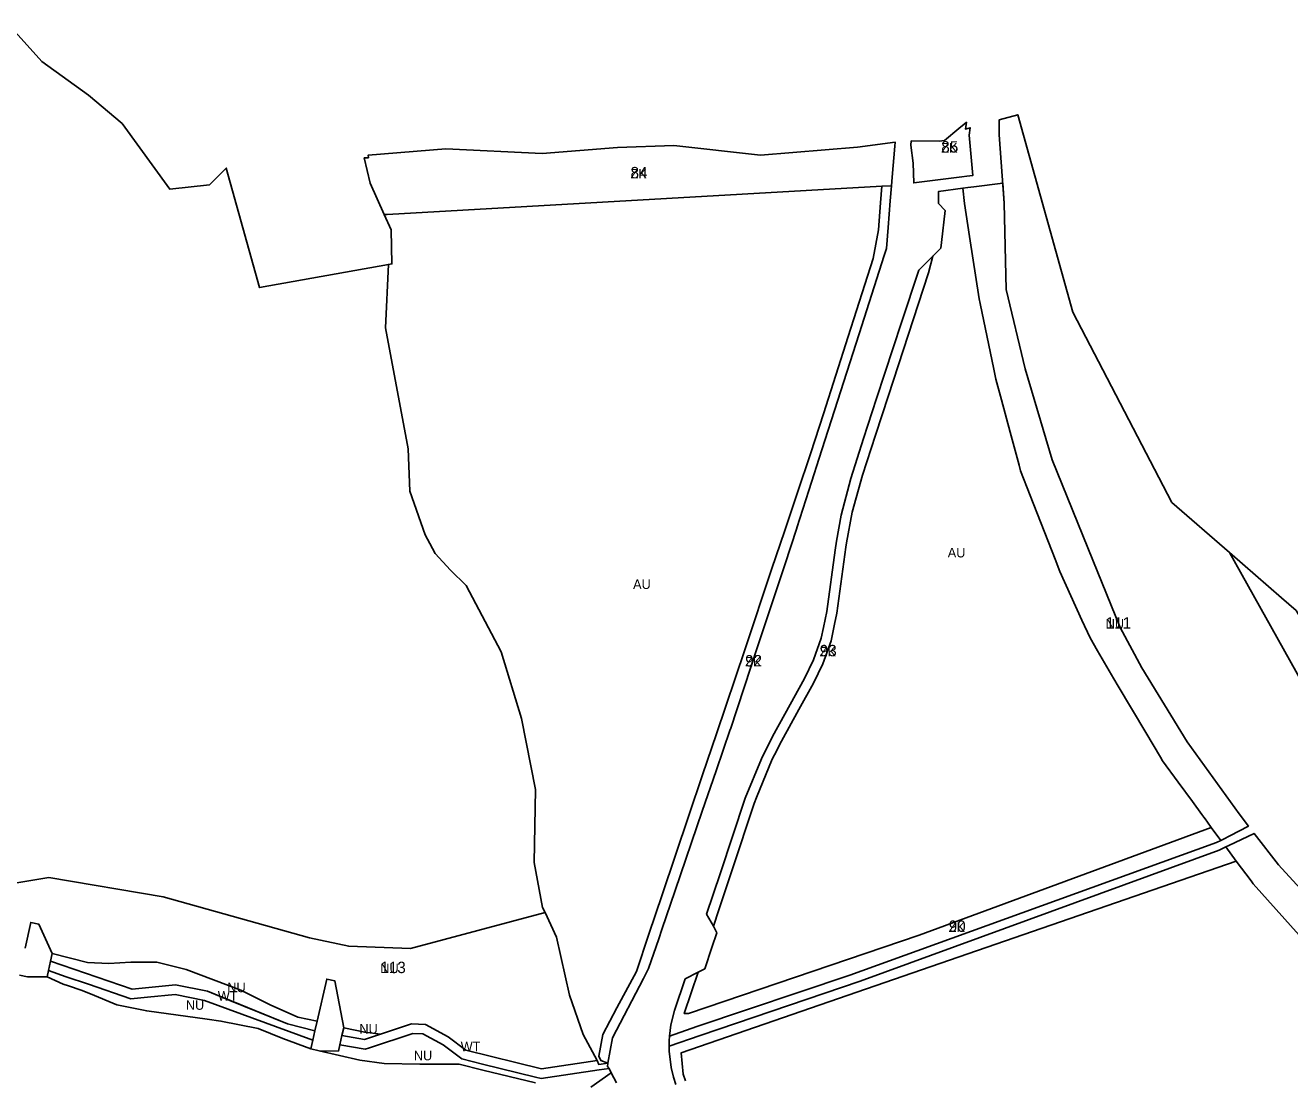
# Model space of a CAD drawing. Extents: x -535894 to -532834, y -1165802 to -1163647.
# Drawn here: x -534347 to -533682, y -1164374 to -1163819 of the extents above; entities that cross this region are included whole.
import ezdxf

# ---------------------------------------------------------------- set-up
doc = ezdxf.new("R2010")
doc.units = 0
for name, color, linetype in [('Vrstva 17', 7, 'Continuous'), ('Vrstva 19', 7, 'Continuous'), ('Vrstva 20', 7, 'Continuous'), ('Vrstva 22', 7, 'Continuous'), ('Vrstva 4', 7, 'Continuous'), ('Vrstva 61', 7, 'Continuous')]:
    doc.layers.add(name, color=color, linetype=linetype)

msp = doc.modelspace()

# ---------------------------------------------------------------- linework, layer by layer
at = {"layer": 'Vrstva 17'}
for points in [[(-533854.784, -1163898.999), (-533880.128, -1163902.177), (-533880.47, -1163891.74), (-533881.62, -1163882.25), (-533881.4, -1163880.05), (-533866.68, -1163880.24), (-533863.98, -1163879.91), (-533856.45, -1163873.6), (-533853.53, -1163871.16), (-533852.38, -1163870.19), (-533852.91, -1163873.85), (-533850.38, -1163873.16), (-533850.88, -1163877.07), (-533849.072, -1163898.259), (-533852.16, -1163898.659)], [(-533891.816, -1163903.599), (-533896.856, -1163903.885), (-534157.028, -1163918.699), (-534158.612, -1163918.789), (-534166.07, -1163902.27), (-534169.16, -1163888.95), (-534166.94, -1163888.88), (-534167.05, -1163887.54), (-534126.29, -1163884.14), (-534075.55, -1163886.63), (-534035.93, -1163883.59), (-534006.23, -1163882.44), (-533960.63, -1163887.47), (-533909.61, -1163883.3), (-533889.94, -1163880.68), (-533890.12, -1163882.84), (-533891.45, -1163899.11)], [(-534019.391, -1164297.188), (-534012.469, -1164276.63), (-533998.41, -1164234.878), (-533991.219, -1164213.523), (-533983.929, -1164191.872), (-533969.039, -1164147.651), (-533954.676, -1164104.997), (-533948.086, -1164085.426), (-533941.36, -1164065.453), (-533934.167, -1164044.089), (-533927.576, -1164023.511), (-533914.601, -1163982.995), (-533901.423, -1163941.848), (-533898.723, -1163926.843), (-533897.565, -1163912.61), (-533896.856, -1163903.885), (-533891.816, -1163903.599), (-533892.46, -1163911.51), (-533893.61, -1163925.64), (-533894.49, -1163936.59), (-533895.7, -1163940.37), (-533908.87, -1163981.51), (-533921.81, -1164021.92), (-533928.41, -1164042.51), (-533935.24, -1164063.87), (-533941.57, -1164083.63), (-533941.6, -1164083.7), (-533947.99, -1164103.02), (-533962.05, -1164145.52), (-533976.56, -1164189.37), (-533976.67, -1164189.68), (-533984.05, -1164211.29), (-533991.32, -1164232.59), (-534005.58, -1164274.33), (-534012.59, -1164294.86), (-534014.24, -1164299.69), (-534019.56, -1164315.28), (-534022.34, -1164320.65), (-534038.5, -1164351.85), (-534040.96, -1164365.04), (-534044.64, -1164363.71), (-534045.792, -1164361.497), (-534043.662, -1164350.075), (-534036.347, -1164335.953), (-534026.028, -1164316.898)], [(-533872.314, -1163949.516), (-533880.349, -1163974.083), (-533893.369, -1164013.891), (-533900.224, -1164034.851), (-533907.102, -1164055.881), (-533912.462, -1164075.297), (-533915.458, -1164091.414), (-533915.767, -1164093.652), (-533920.571, -1164128.488), (-533921.767, -1164134.223), (-533923.6, -1164143.011), (-533927.877, -1164155.133), (-533932.818, -1164165.28), (-533940.474, -1164179.132), (-533949.692, -1164195.811), (-533953.365, -1164202.995), (-533954.52, -1164205.255), (-533962.736, -1164225.379), (-533964.014, -1164228.51), (-533975.657, -1164263.498), (-533982.646, -1164284.498), (-533985.511, -1164293.106), (-533989.076, -1164286.718), (-533982.01, -1164265.485), (-533968.735, -1164225.788), (-533960.244, -1164204.99), (-533954.461, -1164193.275), (-533947.952, -1164181.5), (-533937.612, -1164162.79), (-533932.867, -1164153.046), (-533928.812, -1164141.555), (-533927.645, -1164135.958), (-533925.895, -1164127.567), (-533921.437, -1164095.237), (-533920.792, -1164090.563), (-533918.326, -1164076.951), (-533913.276, -1164057.675), (-533906.483, -1164036.616), (-533899.611, -1164015.605), (-533886.521, -1163975.582), (-533877.501, -1163948.004), (-533870.022, -1163940.58)], [(-534005.963, -1164337.46), (-534000.419, -1164320.801), (-533993.547, -1164317.254), (-534000.781, -1164338.991), (-533998.54, -1164338.94), (-533877.27, -1164297.75), (-533723.64, -1164241.09), (-533718.598, -1164247.919), (-533720.886, -1164249.096), (-533878.291, -1164305.987), (-533913.758, -1164318.806), (-533994.159, -1164345.79), (-534008.513, -1164350.985), (-534007.911, -1164344.987)]]:
    msp.add_lwpolyline(points, close=True, dxfattribs=at)
for points in [[(-533677.32, -1164297.76), (-533701.48, -1164270.84), (-533702.69, -1164269.23), (-533710.415, -1164258.881), (-533716.005, -1164251.393), (-533714.4, -1164250.627), (-533710.987, -1164248.998), (-533701.07, -1164244.265), (-533688.28, -1164260.76), (-533659.7, -1164292.03)], [(-534005.28, -1164376.266), (-534006.517, -1164372.409), (-534007.777, -1164367.311), (-534008.797, -1164358.709), (-534008.777, -1164356.096), (-533992.489, -1164350.51), (-533908.348, -1164321.995), (-533719.497, -1164253.06), (-533716.005, -1164251.393), (-533710.415, -1164258.881), (-534002.49, -1164359.73), (-534001.319, -1164370.935), (-534000.209, -1164374.396)]]:
    msp.add_lwpolyline(points, dxfattribs=at)
at = {"layer": 'Vrstva 19'}
for points in [[(-534355.93, -1163819.24), (-534338.84, -1163838.27), (-534314.16, -1163855.97), (-534296.47, -1163870.97), (-534271.49, -1163905.38), (-534250.57, -1163903.14), (-534241.76, -1163894.34), (-534224.22, -1163957.18), (-534156.41, -1163945.04), (-534157.94, -1163978.43), (-534146.05, -1164041.92), (-534145.18, -1164064.32), (-534137.15, -1164087.2), (-534134.69, -1164091.75), (-534131.77, -1164097.12), (-534123.86, -1164105.89), (-534115.56, -1164113.93), (-534097.11, -1164148.68), (-534086.47, -1164183.86), (-534079.09, -1164221.21), (-534079.7, -1164259.55), (-534075.33, -1164283.15), (-534074.04, -1164285.93), (-534144.82, -1164304.74), (-534177.29, -1164303.6), (-534197.87, -1164299.21), (-534274.99, -1164277.69), (-534335.13, -1164267.45), (-534369.81, -1164273.2)], [(-534079.11, -1164375.48), (-534106.79, -1164368.71), (-534119.2, -1164365.67), (-534136.822, -1164365.594), (-534139.96, -1164365.58), (-534158.72, -1164365.3), (-534171.42, -1164363.56), (-534192.95, -1164358.6), (-534182.72, -1164358.73), (-534181.972, -1164355.438), (-534168.7, -1164357.7), (-534166.42, -1164356.96), (-534143.64, -1164349.5), (-534138.28, -1164349.65), (-534127.7, -1164355.49), (-534117.88, -1164362.9), (-534106.97, -1164365.57), (-534079.15, -1164372.38), (-534076.08, -1164373.13), (-534045.64, -1164368.65), (-534040.3, -1164367.94), (-534039.205, -1164370.137), (-534049.915, -1164377.707)]]:
    msp.add_lwpolyline(points, dxfattribs=at)
for points in [[(-533615.89, -1164239.81), (-533652.75, -1164196.64), (-533675.79, -1164164.9), (-533714.01, -1164096.6), (-533693.46, -1164114.46), (-533686.62, -1164120.4), (-533678.92, -1164127.1), (-533663.1, -1164153.72), (-533640.06, -1164185.46), (-533618.43, -1164210.24), (-533605.59, -1164224.96), (-533602.74, -1164228.22), (-533589.48, -1164241.027), (-533611.129, -1164244.351)], [(-534239.939, -1164332.076), (-534251.65, -1164327.3), (-534268.42, -1164323.97), (-534291.32, -1164326.19), (-534334.234, -1164311.511), (-534333.37, -1164307.48), (-534314.69, -1164312.22), (-534303.58, -1164312.73), (-534291.96, -1164311.97), (-534278.32, -1164311.97), (-534262.91, -1164315.76), (-534234.12, -1164326.63), (-534218.68, -1164334.39), (-534204.157, -1164340.904), (-534193.926, -1164343.087), (-534195.06, -1164348.062), (-534209.55, -1164344.47)], [(-534253.1, -1164332.11), (-534196.171, -1164352.932), (-534197.24, -1164357.62), (-534212.04, -1164352.1), (-534225.01, -1164346.8), (-534244.58, -1164342.94), (-534251.765, -1164341.955), (-534283.55, -1164337.6), (-534299.28, -1164334.42), (-534313.141, -1164328.664), (-534318.04, -1164326.63), (-534324.797, -1164324.417), (-534327.542, -1164323.518), (-534335.99, -1164319.7), (-534335.291, -1164316.439), (-534325.91, -1164319.65), (-534314.28, -1164323.62), (-534291.92, -1164331.27), (-534283.19, -1164330.42), (-534268.67, -1164329.01)], [(-534180.864, -1164350.562), (-534179.95, -1164346.54), (-534168.89, -1164348.83), (-534160.642, -1164349.807), (-534169.08, -1164352.57)]]:
    msp.add_lwpolyline(points, close=True, dxfattribs=at)
at = {"layer": 'Vrstva 20'}
msp.add_lwpolyline([(-533723.64, -1164241.09), (-533723.644, -1164241.091), (-533725.58, -1164238.43), (-533726.88, -1164236.66), (-533727.58, -1164235.7), (-533728.64, -1164234.23), (-533733.546, -1164227.5), (-533740.96, -1164217.33), (-533749.2, -1164206.03), (-533750.29, -1164204.21), (-533758.05, -1164191.21), (-533772.63, -1164166.78), (-533774.86, -1164162.96), (-533783.44, -1164148.24), (-533787.38, -1164141.47), (-533791.66, -1164132.02), (-533803.18, -1164106.57), (-533805.75, -1164099.98), (-533818.83, -1164066.55), (-533823.91, -1164053.54), (-533824.72, -1164050.56), (-533829.37, -1164033.3), (-533833.99, -1164016.17), (-533836.92, -1164005.27), (-533838.01, -1164000.05), (-533845.21, -1163965.55), (-533845.71, -1163963.15), (-533850.77, -1163930.31), (-533853.43, -1163913.02), (-533854.207, -1163904.974), (-533851.572, -1163904.633), (-533848.562, -1163904.243), (-533833.31, -1163902.268), (-533832.51, -1163912.75), (-533831.47, -1163958.19), (-533821.43, -1163999.88), (-533807.37, -1164047.78), (-533785.98, -1164100.6), (-533771.58, -1164135.97), (-533760.11, -1164157.23), (-533736.29, -1164196.18), (-533708.99, -1164234.05), (-533704.042, -1164240.432), (-533713.812, -1164245.458), (-533717.204, -1164247.203), (-533718.598, -1164247.919)], close=True, dxfattribs=at)
msp.add_lwpolyline([(-534369.81, -1164273.2), (-534335.13, -1164267.45), (-534274.99, -1164277.69), (-534197.87, -1164299.21), (-534177.29, -1164303.6), (-534144.82, -1164304.74), (-534074.04, -1164285.93), (-534068.03, -1164298.87), (-534061.1, -1164329.42), (-534054.06, -1164350.04), (-534046.67, -1164363.75), (-534075.84, -1164368.05), (-534115.69, -1164358.28), (-534124.97, -1164351.29), (-534136.93, -1164344.68), (-534144.37, -1164344.48), (-534160.642, -1164349.807), (-534168.89, -1164348.83), (-534179.95, -1164346.54), (-534184.57, -1164321.84), (-534188.86, -1164320.87), (-534193.926, -1164343.087), (-534204.157, -1164340.904), (-534218.68, -1164334.39), (-534234.12, -1164326.63), (-534262.91, -1164315.76), (-534278.32, -1164311.97), (-534291.96, -1164311.97), (-534303.58, -1164312.73), (-534314.69, -1164312.22), (-534333.37, -1164307.48), (-534340.29, -1164292.04), (-534344.59, -1164291.11), (-534347.47, -1164304.55)], dxfattribs=at)
at = {"layer": 'Vrstva 22'}
for points in [[(-534019.391, -1164297.188), (-534026.028, -1164316.898), (-534036.347, -1164335.953), (-534043.662, -1164350.075), (-534045.792, -1164361.497), (-534044.64, -1164363.71), (-534040.96, -1164365.04), (-534045.73, -1164365.82), (-534046.67, -1164363.75), (-534054.06, -1164350.04), (-534061.1, -1164329.42), (-534068.03, -1164298.87), (-534074.04, -1164285.93), (-534075.33, -1164283.15), (-534079.7, -1164259.55), (-534079.09, -1164221.21), (-534086.47, -1164183.86), (-534097.11, -1164148.68), (-534115.56, -1164113.93), (-534123.86, -1164105.89), (-534131.77, -1164097.12), (-534134.69, -1164091.75), (-534137.15, -1164087.2), (-534145.18, -1164064.32), (-534146.05, -1164041.92), (-534157.94, -1163978.43), (-534156.41, -1163945.04), (-534154.6, -1163944.72), (-534154.95, -1163926.9), (-534158.612, -1163918.789), (-534157.028, -1163918.699), (-533896.856, -1163903.885), (-533897.565, -1163912.61), (-533898.723, -1163926.843), (-533901.423, -1163941.848), (-533914.601, -1163982.995), (-533927.576, -1164023.511), (-533934.167, -1164044.089), (-533941.36, -1164065.453), (-533948.086, -1164085.426), (-533954.676, -1164104.997), (-533969.039, -1164147.651), (-533983.929, -1164191.872), (-533991.219, -1164213.523), (-533998.41, -1164234.878), (-534012.469, -1164276.63)], [(-533723.644, -1164241.091), (-533877.27, -1164297.75), (-533998.54, -1164338.94), (-534000.781, -1164338.991), (-533993.547, -1164317.254), (-533990.026, -1164315.437), (-533986.251, -1164304.269), (-533983.622, -1164296.49), (-533985.511, -1164293.106), (-533982.646, -1164284.498), (-533975.657, -1164263.498), (-533964.014, -1164228.51), (-533962.736, -1164225.379), (-533954.52, -1164205.255), (-533953.365, -1164202.995), (-533949.692, -1164195.811), (-533940.474, -1164179.132), (-533932.818, -1164165.28), (-533927.877, -1164155.133), (-533923.6, -1164143.011), (-533921.767, -1164134.223), (-533920.571, -1164128.488), (-533915.767, -1164093.652), (-533915.458, -1164091.414), (-533912.462, -1164075.297), (-533907.102, -1164055.881), (-533900.224, -1164034.851), (-533893.369, -1164013.891), (-533880.349, -1163974.083), (-533872.314, -1163949.516), (-533870.022, -1163940.58), (-533865.909, -1163936.496), (-533865.569, -1163933.561), (-533863.608, -1163916.629), (-533867.045, -1163912.937), (-533866.995, -1163906.624), (-533854.207, -1163904.974), (-533853.43, -1163913.02), (-533850.77, -1163930.31), (-533845.71, -1163963.15), (-533845.21, -1163965.55), (-533838.01, -1164000.05), (-533836.92, -1164005.27), (-533833.99, -1164016.17), (-533829.37, -1164033.3), (-533824.72, -1164050.56), (-533823.91, -1164053.54), (-533818.83, -1164066.55), (-533805.75, -1164099.98), (-533803.18, -1164106.57), (-533791.66, -1164132.02), (-533787.38, -1164141.47), (-533783.44, -1164148.24), (-533774.86, -1164162.96), (-533772.63, -1164166.78), (-533758.05, -1164191.21), (-533750.29, -1164204.21), (-533749.2, -1164206.03), (-533740.96, -1164217.33), (-533733.546, -1164227.5), (-533728.64, -1164234.23), (-533727.58, -1164235.7), (-533726.88, -1164236.66), (-533725.58, -1164238.43)]]:
    msp.add_lwpolyline(points, close=True, dxfattribs=at)
for points in [[(-534000.209, -1164374.396), (-534001.319, -1164370.935), (-534002.49, -1164359.73), (-533710.415, -1164258.881), (-533702.69, -1164269.23), (-533701.48, -1164270.84), (-533677.32, -1164297.76)], [(-534350.52, -1164318.78), (-534346.22, -1164319.71), (-534335.99, -1164319.7), (-534327.542, -1164323.518), (-534324.797, -1164324.417), (-534318.04, -1164326.63), (-534313.141, -1164328.664), (-534299.28, -1164334.42), (-534283.55, -1164337.6), (-534251.765, -1164341.955), (-534244.58, -1164342.94), (-534225.01, -1164346.8), (-534212.04, -1164352.1), (-534197.24, -1164357.62), (-534192.95, -1164358.6), (-534171.42, -1164363.56), (-534158.72, -1164365.3), (-534139.96, -1164365.58), (-534136.822, -1164365.594), (-534119.2, -1164365.67), (-534106.79, -1164368.71), (-534079.11, -1164375.48)], [(-534049.915, -1164377.707), (-534039.205, -1164370.137), (-534036.523, -1164375.518)]]:
    msp.add_lwpolyline(points, dxfattribs=at)
at = {"layer": 'Vrstva 4'}
msp.add_lwpolyline([(-533659.7, -1164292.03), (-533688.28, -1164260.76), (-533701.07, -1164244.265), (-533710.987, -1164248.998), (-533714.4, -1164250.627), (-533716.005, -1164251.393), (-533719.497, -1164253.06), (-533908.348, -1164321.995), (-533992.489, -1164350.51), (-534008.777, -1164356.096), (-534008.751, -1164353.346), (-534008.513, -1164350.985), (-533994.159, -1164345.79), (-533913.758, -1164318.806), (-533878.291, -1164305.987), (-533720.886, -1164249.096), (-533718.598, -1164247.919), (-533717.204, -1164247.203), (-533713.812, -1164245.458), (-533704.042, -1164240.432), (-533708.99, -1164234.05), (-533736.29, -1164196.18), (-533760.11, -1164157.23), (-533771.58, -1164135.97), (-533785.98, -1164100.6), (-533807.37, -1164047.78), (-533821.43, -1163999.88), (-533831.47, -1163958.19), (-533832.51, -1163912.75), (-533835.25, -1163876.86), (-533835.15, -1163868.99), (-533825.35, -1163866.3), (-533796.36, -1163970.1), (-533744.41, -1164070.17), (-533714.01, -1164096.6), (-533675.79, -1164164.9)], dxfattribs=at)
for points in [[(-534196.171, -1164352.932), (-534253.1, -1164332.11), (-534268.67, -1164329.01), (-534283.19, -1164330.42), (-534291.92, -1164331.27), (-534314.28, -1164323.62), (-534325.91, -1164319.65), (-534335.291, -1164316.439), (-534334.234, -1164311.511), (-534291.32, -1164326.19), (-534268.42, -1164323.97), (-534251.65, -1164327.3), (-534209.55, -1164344.47), (-534195.06, -1164348.062)], [(-534180.864, -1164350.562), (-534169.08, -1164352.57), (-534160.642, -1164349.807), (-534144.37, -1164344.48), (-534136.93, -1164344.68), (-534124.97, -1164351.29), (-534115.69, -1164358.28), (-534075.84, -1164368.05), (-534046.67, -1164363.75), (-534045.73, -1164365.82), (-534040.96, -1164365.04), (-534041.28, -1164366.81), (-534040.3, -1164367.94), (-534045.64, -1164368.65), (-534076.08, -1164373.13), (-534079.15, -1164372.38), (-534106.97, -1164365.57), (-534117.88, -1164362.9), (-534127.7, -1164355.49), (-534138.28, -1164349.65), (-534143.64, -1164349.5), (-534166.42, -1164356.96), (-534168.7, -1164357.7), (-534181.972, -1164355.438)]]:
    msp.add_lwpolyline(points, close=True, dxfattribs=at)

# ---------------------------------------------------------------- texts
at = {"layer": 'Vrstva 17'}
for rotation, p in [(359.9999999, (-533865.6229, -1163886.1835)), (360, (-534029.0796, -1163899.7345)), (0, (-533929.549, -1164151.1051)), (360, (-533968.804, -1164156.442)), (0, (-533861.6948, -1164296.0375))]:
    msp.add_text('ZK', height=5, rotation=rotation, dxfattribs=at).set_placement(p)
at = {"layer": 'Vrstva 19'}
for rotation, p in [(0, (-534241.1724, -1164327.771)), (360, (-534263.0108, -1164337.0295)), (360, (-534171.7023, -1164349.555)), (360, (-534143.0539, -1164363.6035))]:
    msp.add_text('NU', height=5, rotation=rotation, dxfattribs=at).set_placement(p)
at = {"layer": 'Vrstva 20'}
for rotation, p in [(0, (-533779.1245, -1164136.5413)), (0.0000001, (-534160.6933, -1164317.75))]:
    msp.add_text('NU', height=5, rotation=rotation, dxfattribs=at).set_placement(p)
at = {"layer": 'Vrstva 22'}
for p in [(-533862.2125, -1164099.1018), (-534027.734, -1164115.6927)]:
    msp.add_text('AU', height=5, rotation=0.0000001, dxfattribs=at).set_placement(p)
at = {"layer": 'Vrstva 4'}
for p in [(-534246.1889, -1164332.2215), (-534118.4277, -1164358.805)]:
    msp.add_text('WT', height=5, rotation=360, dxfattribs=at).set_placement(p)
at = {"layer": 'Vrstva 61'}
for s, rotation, p in [('85', 360, (-533865.6229, -1163886.1835)), ('84', 0.0000001, (-534029.0796, -1163899.7345)), ('111', 0, (-533779.1245, -1164136.5413)), ('93', 360, (-533929.549, -1164151.1051)), ('92', 0, (-533968.804, -1164156.442)), ('90', 0, (-533861.6948, -1164296.0375)), ('113', 0.0000001, (-534160.6933, -1164317.75))]:
    msp.add_text(s, height=6, rotation=rotation, dxfattribs=at).set_placement(p)

doc.saveas('drawing.dxf')
